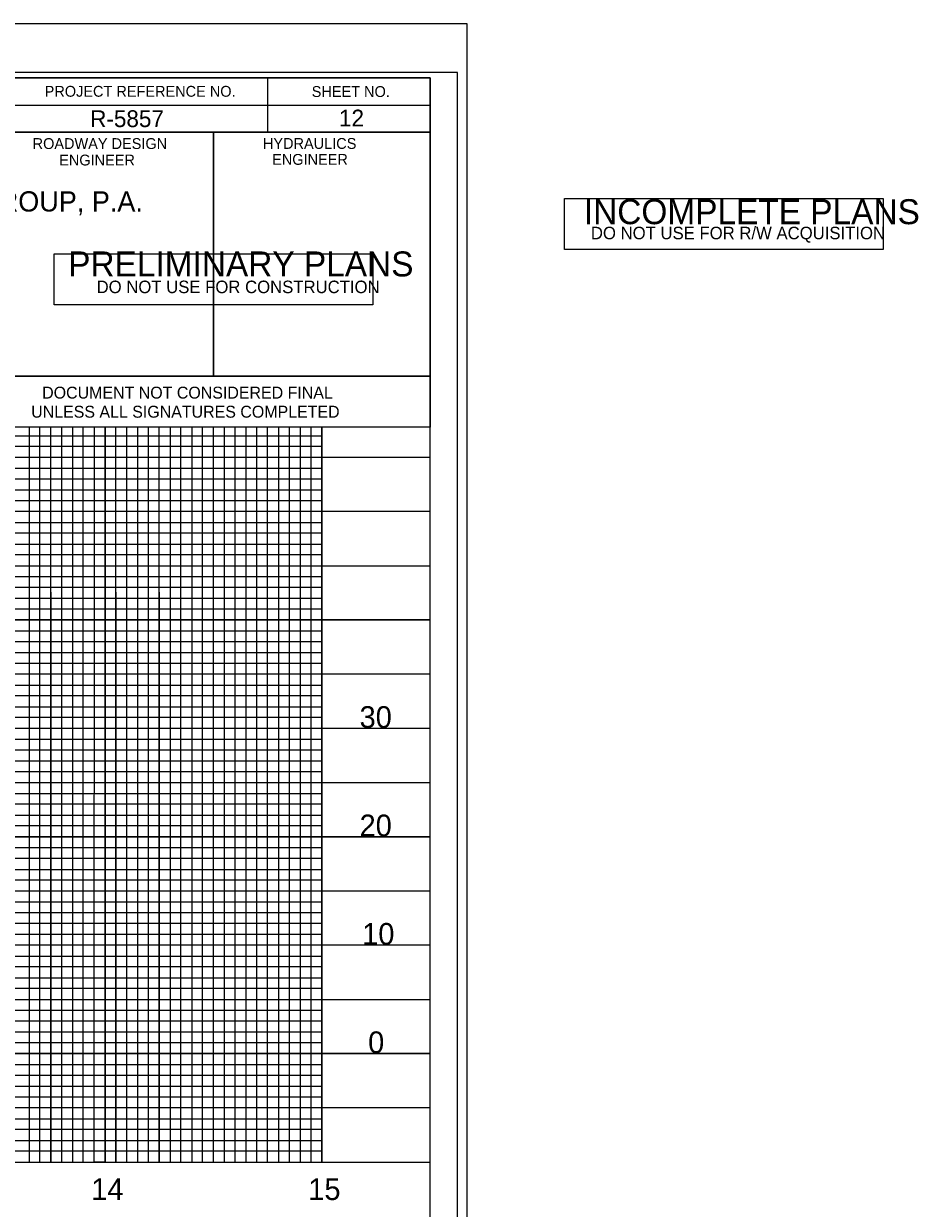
# Model space of a CAD drawing. Extents: x 2180324 to 2182216, y 74532 to 75632.
# Drawn here: x 2181803 to 2182216, y 75086 to 75632 of the extents above; entities that cross this region are included whole.
import ezdxf

# ---------------------------------------------------------------- set-up
doc = ezdxf.new("R2010")
doc.units = 0
for name, color, linetype in [('Exist Structure Minor Culvert Topo', 7, 'Continuous'), ('Exist Structure Minor Culvert Topo Terminator', 7, 'Continuous'), ('Exist Structure Minor Footbridge', 7, 'Continuous'), ('Old_Level_1', 7, 'Continuous'), ('Old_Level_11', 7, 'Continuous'), ('Old_Level_2', 7, 'Continuous'), ('Old_Level_3', 7, 'Continuous'), ('Prop North Arrow NAD83 for Plan Sheets CELL', 7, 'Continuous'), ('Scratch_Level_0', 7, 'Continuous'), ('Sheet Cutting Line CELL', 7, 'Continuous'), ('Sheet Data Field CELL', 7, 'Continuous'), ('Sheet Plan CELL', 7, 'Continuous'), ('Sheet Plot Border Inside CELL', 7, 'Continuous'), ('Sheet Plot Border Outside CELL', 7, 'Continuous'), ('Sheet Sticker Exception Certification CELL', 7, 'Continuous'), ('Sheet Sticker Incomplete CELL', 7, 'Continuous'), ('Sheet Sticker Preliminary CELL', 7, 'Continuous')]:
    doc.layers.add(name, color=color, linetype=linetype)

msp = doc.modelspace()

# ---------------------------------------------------------------- linework, layer by layer
at = {"layer": 'Exist Structure Minor Culvert Topo'}
msp.add_lwpolyline([(2181300.9, 75607.28), (2181300.9, 75107.28), (2181940.9, 75107.28), (2181940.9, 75446.23), (2181790.85, 75446.23), (2181790.85, 75607.28)], close=True, dxfattribs=at)
at = {"layer": 'Exist Structure Minor Footbridge'}
msp.add_lwpolyline([(2181817.42, 75502.57), (2181817.42, 75526.07), (2181964.42, 75526.07), (2181964.42, 75502.57)], close=True, dxfattribs=at)
at = {"layer": 'Old_Level_11'}
for p, q in [((2181840.9, 75107.28), (2181840.9, 75446.23)), ((2181890.9, 75107.28), (2181890.9, 75446.23)), ((2181940.9, 75107.28), (2181940.9, 75446.23)), ((2181990.9, 75407.28), (2180490.9, 75407.28)), ((2181990.9, 75357.28), (2180490.9, 75357.28)), ((2181990.9, 75307.28), (2180490.9, 75307.28)), ((2181990.9, 75257.28), (2180490.9, 75257.28)), ((2181990.9, 75207.28), (2180490.9, 75207.28)), ((2181990.9, 75157.28), (2180490.9, 75157.28))]:
    msp.add_line(p, q, dxfattribs=at)
at = {"layer": 'Old_Level_2'}
for points in [[(2181265.9, 75107.28), (2181315.9, 75107.28), (2181315.9, 75607.28), (2181365.9, 75607.28), (2181365.9, 75107.28), (2181415.9, 75107.28), (2181415.9, 75607.28), (2181465.9, 75607.28), (2181465.9, 75107.28), (2181515.9, 75107.28), (2181515.9, 75607.28), (2181565.9, 75607.28), (2181565.9, 75107.28), (2181615.9, 75107.28), (2181615.9, 75607.28), (2181665.9, 75607.28), (2181665.9, 75107.28), (2181715.9, 75107.28), (2181715.9, 75607.28), (2181765.9, 75607.28), (2181765.9, 75107.28), (2181815.9, 75107.28), (2181815.9, 75446.23)], [(2181815.9, 75370.08), (2181815.9, 75107.28), (2181865.9, 75107.28), (2181865.9, 75446.23)], [(2181865.9, 75370.08), (2181865.9, 75107.28), (2181915.9, 75107.28), (2181915.9, 75446.23)], [(2181990.9, 75432.28), (2180490.9, 75432.28), (2180490.9, 75382.28), (2181815.9, 75382.28)], [(2181815.9, 75382.28), (2181990.9, 75382.28)], [(2181990.9, 75332.28), (2180490.9, 75332.28), (2180490.9, 75282.28), (2181990.9, 75282.28)], [(2181990.9, 75232.28), (2180490.9, 75232.28), (2180490.9, 75182.28), (2181990.9, 75182.28)], [(2181990.9, 75132.28), (2180490.9, 75132.28)]]:
    msp.add_lwpolyline(points, dxfattribs=at)
at = {"layer": 'Prop North Arrow NAD83 for Plan Sheets CELL'}
msp.add_lwpolyline([(2182052.76, 75528.12), (2182052.76, 75551.62), (2182199.76, 75551.62), (2182199.76, 75528.12)], close=True, dxfattribs=at)
at = {"layer": 'Scratch_Level_0'}
msp.add_line((2182007.9, 75632.28), (2180323.9, 75632.28), dxfattribs=at)
at = {"layer": 'Sheet Cutting Line CELL'}
for p, q in [((2181915.9, 75607.23), (2181915.9, 75582.23)), ((2181790.85, 75594.73), (2181990.9, 75594.73)), ((2181890.9, 75582.23), (2181890.9, 75469.78)), ((2180490.9, 75107.28), (2181990.9, 75107.28))]:
    msp.add_line(p, q, dxfattribs=at)
for points in [[(2181990.9, 75607.28), (2180490.9, 75607.28), (2180490.9, 74557.28), (2181990.9, 74557.28)], [(2181790.85, 75607.28), (2181990.9, 75607.28), (2181990.9, 75582.23), (2181790.85, 75582.23)], [(2181790.85, 75582.23), (2181890.9, 75582.23), (2181890.9, 75469.73), (2181790.85, 75469.73)], [(2181890.9, 75582.23), (2181990.9, 75582.23), (2181990.9, 75469.73), (2181890.9, 75469.73)]]:
    msp.add_lwpolyline(points, close=True, dxfattribs=at)
at = {"layer": 'Sheet Data Field CELL'}
for p, q in [((2181790.85, 75469.73), (2181990.89, 75469.73)), ((2181790.85, 75469.73), (2181990.89, 75469.73)), ((2181990.89, 75469.72), (2181990.89, 75446.22)), ((2181990.89, 75469.72), (2181990.89, 75446.22)), ((2181990.89, 75446.23), (2181790.85, 75446.23)), ((2181990.89, 75446.23), (2181790.85, 75446.23))]:
    msp.add_line(p, q, dxfattribs=at)
at = {"layer": 'Sheet Plot Border Inside CELL'}
msp.add_lwpolyline([(2180540.9, 75446.23), (2180540.9, 75107.28), (2181940.9, 75107.28), (2181940.9, 75446.23)], dxfattribs=at)
at = {"layer": 'Sheet Plot Border Outside CELL'}
for p, q in [((2180540.9, 75442.28), (2181940.9, 75442.28)), ((2181940.9, 75422.28), (2180540.9, 75422.28)), ((2180540.9, 75417.28), (2181940.9, 75417.28)), ((2181940.9, 75397.28), (2180540.9, 75397.28)), ((2180540.9, 75392.28), (2181940.9, 75392.28)), ((2181940.9, 75372.28), (2180540.9, 75372.28)), ((2180540.9, 75367.28), (2181940.9, 75367.28)), ((2181940.9, 75362.28), (2180540.9, 75362.28)), ((2180540.9, 75352.28), (2181940.9, 75352.28)), ((2181940.9, 75347.28), (2180540.9, 75347.28)), ((2180540.9, 75342.28), (2181940.9, 75342.28)), ((2181940.9, 75337.28), (2180540.9, 75337.28)), ((2180540.9, 75327.28), (2181940.9, 75327.28)), ((2181940.9, 75322.28), (2180540.9, 75322.28)), ((2180540.9, 75317.28), (2181940.9, 75317.28)), ((2181940.9, 75312.28), (2180540.9, 75312.28)), ((2180540.9, 75302.28), (2181940.9, 75302.28)), ((2181940.9, 75297.28), (2180540.9, 75297.28)), ((2180540.9, 75292.28), (2181940.9, 75292.28)), ((2181940.9, 75287.28), (2180540.9, 75287.28)), ((2180540.9, 75277.28), (2181940.9, 75277.28)), ((2181940.9, 75272.28), (2180540.9, 75272.28)), ((2180540.9, 75267.28), (2181940.9, 75267.28)), ((2181940.9, 75262.28), (2180540.9, 75262.28)), ((2180540.9, 75252.28), (2181940.9, 75252.28)), ((2181940.9, 75247.28), (2180540.9, 75247.28)), ((2180540.9, 75242.28), (2181940.9, 75242.28)), ((2181940.9, 75237.28), (2180540.9, 75237.28)), ((2180540.9, 75227.28), (2181940.9, 75227.28)), ((2181940.9, 75222.28), (2180540.9, 75222.28)), ((2181940.9, 75217.28), (2180540.9, 75217.28)), ((2181940.9, 75212.28), (2180540.9, 75212.28)), ((2180540.9, 75202.28), (2181940.9, 75202.28)), ((2181940.9, 75197.28), (2180540.9, 75197.28)), ((2180540.9, 75192.28), (2181940.9, 75192.28)), ((2181940.9, 75187.28), (2180540.9, 75187.28)), ((2180540.9, 75177.28), (2181940.9, 75177.28)), ((2181940.9, 75172.28), (2180540.9, 75172.28)), ((2180540.9, 75167.28), (2181940.9, 75167.28)), ((2181940.9, 75162.28), (2180540.9, 75162.28)), ((2180540.9, 75152.28), (2181940.9, 75152.28)), ((2181940.9, 75147.28), (2180540.9, 75147.28)), ((2180540.9, 75142.28), (2181940.9, 75142.28)), ((2181940.9, 75137.28), (2180540.9, 75137.28)), ((2180540.9, 75127.28), (2181940.9, 75127.28)), ((2181940.9, 75122.28), (2180540.9, 75122.28)), ((2180540.9, 75117.28), (2181940.9, 75117.28))]:
    msp.add_line(p, q, dxfattribs=at)
for points in [[(2181805.9, 75446.23), (2181805.9, 75107.28), (2181810.9, 75107.28), (2181810.9, 75446.23)], [(2181820.9, 75446.23), (2181820.9, 75107.28), (2181820.9, 75107.28), (2181825.9, 75107.28), (2181830.9, 75107.28), (2181830.9, 75446.23)], [(2181825.9, 75446.23), (2181825.9, 75107.28)], [(2181835.9, 75446.23), (2181835.8, 75107.33), (2181840.8, 75107.33), (2181845.9, 75107.28), (2181845.9, 75446.23)], [(2181845.9, 75370.08), (2181845.9, 75107.28), (2181850.9, 75107.28), (2181850.9, 75446.23)], [(2181855.9, 75446.23), (2181855.9, 75107.28), (2181860.9, 75107.28), (2181860.9, 75446.23)], [(2181870.9, 75446.23), (2181870.9, 75107.28), (2181875.9, 75107.28), (2181875.9, 75446.23)], [(2181880.9, 75446.23), (2181880.9, 75107.28), (2181885.9, 75107.28), (2181885.9, 75446.23)], [(2181895.9, 75446.23), (2181895.9, 75107.28), (2181900.9, 75107.28), (2181900.9, 75446.23)], [(2181905.9, 75446.23), (2181905.9, 75107.28), (2181910.9, 75107.28), (2181910.9, 75446.23)], [(2181920.9, 75446.23), (2181920.9, 75107.28), (2181925.9, 75107.28), (2181925.9, 75446.23)], [(2181930.9, 75446.23), (2181930.9, 75107.28), (2181935.9, 75107.28), (2181935.9, 75446.23)], [(2181940.9, 75437.28), (2180540.9, 75437.28), (2180540.9, 75427.28), (2181940.9, 75427.28)], [(2181940.9, 75412.28), (2180540.9, 75412.28), (2180540.9, 75402.28), (2181940.9, 75402.28)], [(2181940.9, 75387.28), (2180540.9, 75387.28), (2180540.9, 75377.28), (2181940.9, 75377.28)], [(2181940.9, 75112.28), (2180540.9, 75112.28)]]:
    msp.add_lwpolyline(points, dxfattribs=at)
at = {"layer": 'Sheet Sticker Exception Certification CELL'}
for points in [[(2181240.9, 75107.28), (2181290.9, 75107.28), (2181290.9, 75607.28), (2181340.9, 75607.28), (2181340.9, 75107.28), (2181390.9, 75107.28), (2181390.9, 75607.28), (2181440.9, 75607.28), (2181440.9, 75107.28), (2181490.9, 75107.28), (2181490.9, 75607.28), (2181540.9, 75607.28), (2181540.9, 75107.28), (2181590.9, 75107.28), (2181590.9, 75607.28), (2181640.9, 75607.28), (2181640.9, 75107.28), (2181690.9, 75107.28), (2181690.9, 75607.28), (2181740.9, 75607.28), (2181740.9, 75107.28), (2181790.9, 75107.28), (2181790.9, 75607.28), (2181817.2, 75607.28)], [(2181940.9, 75446.23), (2181940.9, 75107.28), (2181990.9, 75107.28), (2181990.9, 75457.28)], [(2181840.9, 75446.23), (2181840.9, 75107.28), (2181890.9, 75107.28), (2181890.9, 75107.28), (2181890.9, 75446.23)], [(2181990.9, 75407.28), (2180490.9, 75407.28), (2180490.9, 75357.28), (2181990.9, 75357.28)], [(2181990.9, 75307.28), (2180490.9, 75307.28), (2180490.9, 75257.28), (2181990.9, 75257.28)], [(2181990.9, 75207.28), (2180490.9, 75207.28), (2180490.9, 75207.28), (2180490.9, 75157.28), (2181990.9, 75157.28)]]:
    msp.add_lwpolyline(points, dxfattribs=at)
at = {"layer": 'Sheet Sticker Incomplete CELL'}
msp.add_lwpolyline([(2180323.9, 74532.28), (2182007.9, 74532.28), (2182007.9, 75632.28), (2180323.9, 75632.28)], close=True, dxfattribs=at)
at = {"layer": 'Sheet Sticker Preliminary CELL'}
msp.add_lwpolyline([(2180336.9, 74554.73), (2182003.4, 74554.73), (2182003.4, 75609.83), (2180336.9, 75609.83)], close=True, dxfattribs=at)

# ---------------------------------------------------------------- texts
at = {"layer": 'Exist Structure Minor Culvert Topo Terminator'}
msp.add_text('SUNGATE DESIGN GROUP, P.A.', height=9.3194, dxfattribs=at).set_placement((2181667.25, 75545.66))
at = {"layer": 'Exist Structure Minor Footbridge'}
for s, height, p in [('PRELIMINARY PLANS', 11.52, (2181823.92, 75515.72)), ('DO NOT USE FOR CONSTRUCTION', 5.76, (2181837.02, 75508.02))]:
    msp.add_text(s, height=height, dxfattribs=at).set_placement(p)
at = {"layer": 'Old_Level_1'}
for s, p in [('14', (2181834.55, 75089.78)), ('15', (2181934.64, 75089.78))]:
    msp.add_text(s, height=10, dxfattribs=at).set_placement(p)
at = {"layer": 'Old_Level_3'}
for s, p in [('30', (2181958.29, 75307.53)), ('20', (2181958.29, 75257.53)), ('10', (2181959.49, 75207.53)), ('0', (2181962.24, 75157.53))]:
    msp.add_text(s, height=10, dxfattribs=at).set_placement(p)
at = {"layer": 'Prop North Arrow NAD83 for Plan Sheets CELL'}
for s, height, p in [('INCOMPLETE PLANS', 11.52, (2182061.71, 75539.82)), ('DO NOT USE FOR R/W ACQUISITION', 5.76, (2182064.96, 75532.87))]:
    msp.add_text(s, height=height, dxfattribs=at).set_placement(p)
at = {"layer": 'Sheet Cutting Line CELL'}
for s, height, p in [('PROJECT REFERENCE NO.', 5.0001, (2181813.07, 75598.59)), ('SHEET NO.', 5, (2181936.22, 75598.49)), ('ROADWAY DESIGN', 5.0001, (2181807.52, 75574.49)), ('HYDRAULICS', 5, (2181913.72, 75574.54)), ('ENGINEER', 5, (2181819.77, 75566.89)), ('ENGINEER', 5, (2181917.97, 75567.19))]:
    msp.add_text(s, height=height, dxfattribs=at).set_placement(p)
at = {"layer": 'Sheet Data Field CELL'}
for s, p in [('DOCUMENT NOT CONSIDERED FINAL', (2181811.92, 75459.38)), ('DOCUMENT NOT CONSIDERED FINAL', (2181811.92, 75459.38)), ('UNLESS ALL SIGNATURES COMPLETED', (2181806.85, 75450.58)), ('UNLESS ALL SIGNATURES COMPLETED', (2181806.85, 75450.58))]:
    msp.add_text(s, height=5.5, dxfattribs=at).set_placement(p)
at = {"layer": 'Sheet Plan CELL'}
for s, p in [('R-5857', (2181834.07, 75584.59)), ('12', (2181948.8, 75584.89))]:
    msp.add_text(s, height=7.75, dxfattribs=at).set_placement(p)

doc.saveas('drawing.dxf')
